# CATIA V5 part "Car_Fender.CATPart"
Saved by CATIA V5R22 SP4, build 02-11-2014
Part number: Car_Fender
Material "ｱﾙﾐﾆｳﾑ": density 2710 kg/m3, Young's modulus 7e+10 Pa, Poisson ratio 0.346, thermal expansion 2.36e-05 1/K
Bounding box of the stored display mesh (mm): x -800 to 0, y -40 to 122.298, z 0 to 580
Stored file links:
  \\172.16.16.24\714_東北電子専門学校\2014年度\02_実施プロセス\catia_model_data\Car_ASSY\CAE_data\Car_Fender.CATPart
  C:\Program Files\Dassault Systemes\B22\win_b64\startup\materials\red_env_512x512.jpg
  C:\Program Files\Dassault Systemes\B22\win_b64\startup\materials\yellow_env_512x512.jpg

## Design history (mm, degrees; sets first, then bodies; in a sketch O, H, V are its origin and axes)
Set1
  Plane1: type Offset, RefPlane yz-plane, Offset 400, reversed
  Plane2 "平面.2": type Offset, RefPlane Plane1, Offset 400, reversed
Body1 (main body)
  Body2
    Sketch1 on yz-plane, origin (0, 0, 0), H (0, 1, 0), V (0, 0, 1)
      point P1 (40.1932, 0)
      point P2 (100, 50)
      line L1 (100, 50) -> (100, 0)
      point P3 (100, 0)
      line L2 (100, 0) -> (0, 0)
      line L3 (0, 0) -> (0, 450)
      line L4 (0, 450) -> (10, 450)
      point P5 (10, 450)
      spline S1 through (10, 450) (100, 50)
      point P6 (10, 450)
      point P7 (100, 50)
      length L3 = 450
      length L2 = 100
      length L1 = 50
      length L4 = 10
      coincidence: P3 H, P6 P5, P7 P2
      vertical: L1 V, L3 V
      horizontal: L2 H, L4 H
    Sketch2 on Plane1, origin (-400, 0, 0), H (0, 1, 0), V (0, 0, 1)
      point P1 (40.1932, 0)
      point P2 (100, 50)
      line L1 (100, 50) -> (100, 0)
      point P3 (100, 0)
      line L2 (100, 0) -> (0, 0)
      line L3 (0, 0) -> (0, 530)
      line L4 (0, 530) -> (10, 530)
      point P5 (10, 530)
      spline S1 through (10, 530) (100, 50)
      point P6 (10, 530)
      point P7 (100, 50)
      length L3 = 530
      length L2 = 100
      length L1 = 50
      length L4 = 10
      coincidence: P3 H, P6 P5, P7 P2
      vertical: L1 V, L3 V
      horizontal: L2 H, L4 H
    Sketch3 on Plane2, origin (-800, 0, 0), H (0, 1, 0), V (0, 0, 1)
      point P1 (40.1932, 0)
      point P2 (100, 50)
      line L1 (100, 50) -> (100, 0)
      point P3 (100, 0)
      line L2 (100, 0) -> (0, 0)
      line L3 (0, 0) -> (0, 580)
      line L4 (0, 580) -> (10, 580)
      point P5 (10, 580)
      spline S1 through (10, 580) (100, 50)
      point P6 (10, 580)
      point P7 (100, 50)
      length L3 = 580
      length L2 = 100
      length L1 = 50
      length L4 = 10
      coincidence: P3 H, P6 P5, P7 P2
      vertical: L1 V, L3 V
      horizontal: L2 H, L4 H
    Loft1: solid, Sections (Sketch1; Sketch2; Sketch3)
    Body3
      Sketch4 on zx-plane, origin (0, 0, 0), H (-1, 0, 0), V (0, 0, 1)
        line L1 (-46.4952, 240) -> (159.0779, 240)
        arc A1 centre (390, 110) radius 265 from (159.0779, 240) to (655, 109.9999) cw
        point P2 (390, 110)
        line L2 (655, 109.9999) -> (655, -30)
        line L3 (-37.8358, 626.6258) -> (859.9489, 626.6258)
        line L4 (859.9489, 626.6258) -> (850, -30)
        line L5 (850, -30) -> (655, -30)
        line L6 (-37.8358, 626.6258) -> (-46.4952, 240)
        radius A1 = 265
        distance P2 H = 110
        distance V P2 = 390
        distance H L1 = 240
        horizontal: L1 H, L3 H, L5 H
        tangency: L2 A1
        vertical: L2 V
      Pad1: profile Sketch4, direction (0, 1, 0), length 340, mirrored extent
    Intersect1: tool Body3
    Sketch5 on Plane2, origin (-800, 0, 0), H (0, 1, 0), V (0, 0, 1)
      line L1 (0, 580) -> (0, 545)
      line L2 (-5, 540) -> (-40, 540)
      point P2 (-40, 540)
      reference projected line E1 (10, 580) -> (0, 580) from edge [face of Loft1 | face of Loft1]
      reference intersected line E2 (0, 0) -> (0, 580) from face of Loft1
      arc A1 centre (-5, 545) radius 5 from (-5, 540) to (0, 545) ccw
      line L3 (-5, 537) -> (-40, 537)
      arc A2 centre (-5, 545) radius 8 from (-5, 537) to (3, 545) ccw
      line L4 (3, 580) -> (3, 545)
      line L5 (-40, 537) -> (-40, 540)
      line L6 (3, 580) -> (0, 580)
      reference projected line E3 (10, 580) -> (0, 580) from edge [face of Loft1 | face of Loft1]
      distance E1 L2 = 40
      radius A1 = 5
      distance L1 P2 = 40
      length L5 = 3
      length L6 = 3
      radius A2 = 8
      vertical: L1 V, L4 V, L5 V
      horizontal: L2 H, L6 H, L3 H
      coincidence: L1 E2, L6 E3
      tangency: A1 L2, A1 L1, L4 A2, A2 L3
    Shell1: ExtOffset 0, Face (face of Loft1; face of Loft1; face of Pad1 from Sketch4.A1; face of Loft1; face of Pad1 from Sketch4.L1; face of Loft1), IntOffset 3
    Rib1: profile Sketch5, centre curve edge [face of Loft1 | face of Loft1]
    Sketch6 on Plane2, origin (-800, 0, 0), H (0, 1, 0), V (0, 0, 1)
      projected line E1 (97, 0) -> (97, 50) from edge [face of Shell1 | face of Rib1]
      projected curve E2 from edge [face of Shell1 | face of Rib1]
      projected line E3 (10, 576.9862) -> (3, 576.9862) from edge [face of Shell1 | face of Rib1]
      point P6 (3, 576.9862)
      projected line E4 (3, 576.9862) -> (3, 545) from edge [face of Rib1 | face of Rib1]
      projected line E5 (3, 576.9862) -> (3, 399.233) from edge [face of Rib1 | face of Rib1]
      point P7 (3, 576.9862)
      line L1 (97, 0) -> (37, 0)
      line L2 (37, 0) -> (17.9077, 155.4943)
      arc A1 centre (2003, 399.233) radius 2000 from (17.9077, 155.4943) to (3, 399.233) cw
      angle L1 L2 = 97
      length L1 = 60
      radius A1 = 2000
      horizontal: L1 H
      coincidence: P6 P7
      tangency: A1 L2, A1 E4
    Pad2: profile Sketch6, direction (1, 0, 0), length 10, opposite side length -7
    Sketch7 on yz-plane, origin (0, 0, 0), H (0, 1, 0), V (0, 0, 1)
      projected curve E1 from edge [face of Loft1 | face of Shell1]
      projected curve E2 from edge [face of Loft1 | face of Shell1]
      line L1 (103.8705, 240) -> (92.1161, 240)
      line L2 (89.1161, 237) -> (89.1161, 160)
      line L3 (89.1161, 160) -> (86.1161, 160)
      line L4 (86.1161, 160) -> (86.1161, 237)
      line L5 (92.1161, 243) -> (100.927, 243)
      offset curve E3 from edge [face of Loft1 | face of Shell1]
      offset curve E4 from edge [face of Loft1 | face of Shell1]
      line L6 (101.1109, 260) -> (104.111, 260)
      reference projected line E5 (0, 240) -> (106.8716, 240) from edge [face of Pad1 from Sketch4.L1 | face of Loft1]
      arc A1 centre (92.1161, 237) radius 3 from (89.1161, 237) to (92.1161, 240) cw
      arc A2 centre (92.1161, 237) radius 6 from (86.1161, 237) to (92.1161, 243) cw
      length L3 = 3
      length L6 = 3
      distance L5 L1 = 3
      distance E5 L3 = 80
      distance L2 E1 = 15
      radius A1 = 3
      radius A2 = 6
      horizontal: L1 H, L3 H, L5 H, L6 H
      vertical: L2 V, L4 V
      tangency: A1 L2, A1 L1, A2 L4, A2 L5
    Rib2: profile Sketch7, centre curve edge [face of Pad1 from Sketch4.L1 | face of Shell1]
    Body4
      Sketch8 on zx-plane, origin (0, 0, 0), H (-1, 0, 0), V (0, 0, 1)
        point P1 (0, 300)
        line L1 (0, 300) -> (127.0171, 520)
        line L2 (127.0171, 520) -> (-100, 520)
        line L3 (-100, 520) -> (-100, 300)
        line L4 (-100, 300) -> (0, 300)
        angle L1 L4 = 120
        distance L4 H = 300
        coincidence: P1 V
        horizontal: L2 H, L4 H
        vertical: L3 V
      Pad3: profile Sketch8, direction (0, 1, 0), length 218, mirrored extent
    Remove1: tool Body4
    Sketch9 on xy-plane, origin (0, 0, 0), H (1, 0, 0), V (0, 1, 0)
      line L1 (-730, -50) -> (-730, -25)
      arc A1 centre (-725, -25) radius 5 from (-730, -25) to (-720, -25) cw
      point P3 (-725, -25)
      line L2 (-720, -25) -> (-720, -50)
      line L3 (-720, -50) -> (-730, -50)
      reference projected line E1 (-800, -40) -> (-800, -5) from edge [face of Rib1 | face of Rib1]
      reference projected line E2 (-5.7993, -40) -> (-800, -40) from edge [face of Rib1 | face of Rib1]
      distance E1 L1 = 70
      length L3 = 10
      distance P3 E2 = 15
      radius A1 = 5
      vertical: L1 V
      tangency: A1 L1, L2 A1
      horizontal: L3 H
    Pocket1: profile Sketch9, direction (0, 0, 1), length 657
    RectPattern1: of Pocket1, direction 1 instances 3, spacing 270, along X axis
    Sketch10 on {plane type Tangent, Support face of Rib2, RefPoint {point type OnSurface, Support face of Rib2, RefPoint {point stored without definition}, Length 0, Direction (0, 0, -1000)}}, origin (-34.1531, 89.7232, 188.2636), H (0.9999, -0.0168, 0), V (0, 0, 1)
      point P1 (-15.8415, 1.7364)
      reference projected line E1 (-124.8302, -28.2636) -> (34.1585, -28.2636) from edge [face of Rib2 | face of Rib2]
      reference projected line E2 (34.1585, -28.2636) -> (34.1585, 48.7364) from edge [face of Rib2 | face of Rib2]
      distance P1 E1 = 30
      distance P1 E2 = 50
    Hole1: placed by Sketch10, at (-49.9925, 89.9835, 190) direction (-0.016, -0.9999, 0), diameter 15, through (limit type 3)
    Fillet1: radius 10, on edge [face of Rib1 | face of Rib1]; edge [face of Rib1 | face of Pad3 from Sketch8.L1]
    Chamfer1: length 70, angle 35, on edge [face of Rib2 | face of Rib2]
    Fillet2: radius 5, on edge [face of Rib2 | face of Rib2]; edge [face of Chamfer1 | face of Rib2]; edge [face of Rib2 | face of Chamfer1]
    Fillet3: radius 10, on edge [face of Pad1 from Sketch4.L2 | face of Pad2]
  Add1: tool Body2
